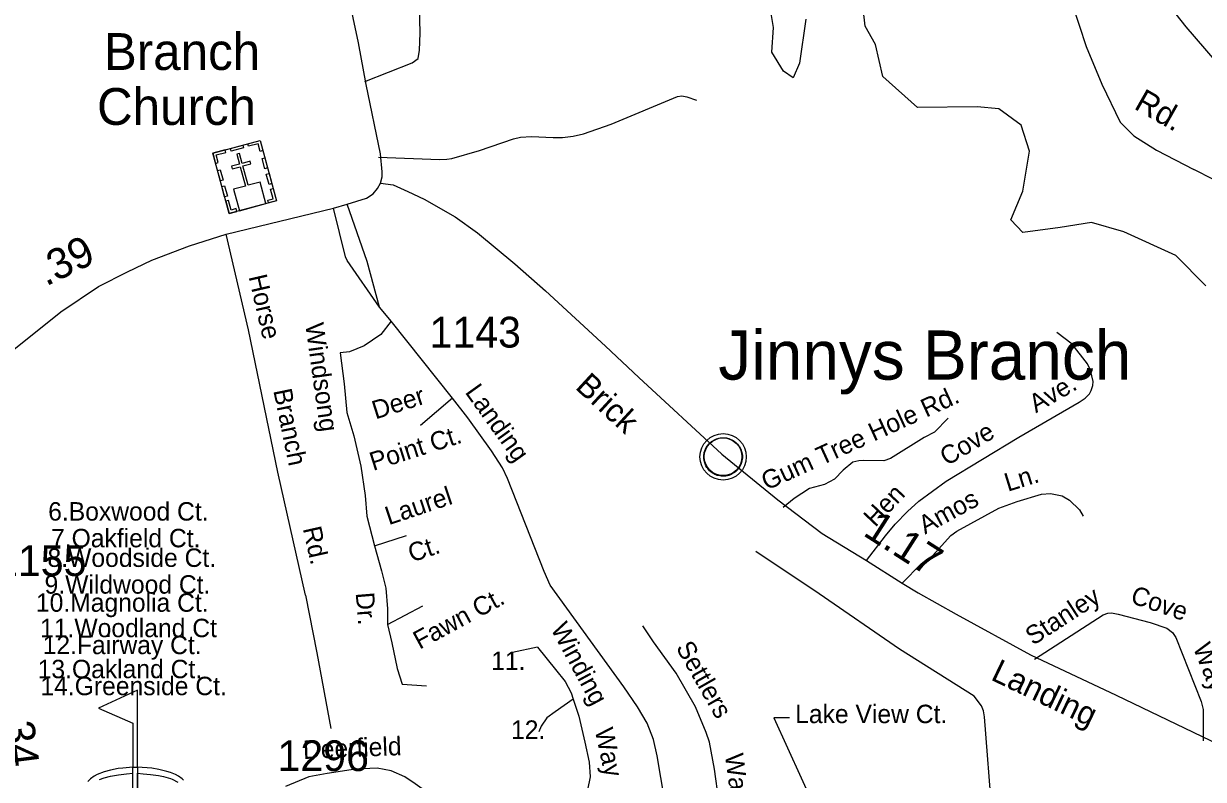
# Model space of a CAD drawing. Extents: x 2104537 to 2336408, y 34176 to 229611.
# Drawn here: x 2178229 to 2183028, y 59376 to 62451 of the extents above; entities that cross this region are included whole.
import ezdxf

# ---------------------------------------------------------------- set-up
doc = ezdxf.new("R2010")
doc.units = 0
for name, color, linetype in [('Exist Civil Demographics Community CELL', 7, 'Continuous'), ('Exist Civil Demographics Community Label', 7, 'Continuous'), ('Exist Cultural Church with Cemetary CELL', 7, 'Continuous'), ('Exist Cultural Church with Cemetery Label', 7, 'Continuous'), ('Exist Cultural Recreational Golf Course CELL', 7, 'Continuous'), ('Exist Hydrographic Creek Single Shore', 7, 'Continuous'), ('Exist Road Non-System Type 51', 7, 'Continuous'), ('Exist Road Non-System Type 51 Label', 7, 'Continuous'), ('Exist Road Primary NC Attributed', 7, 'Continuous'), ('Exist Road Primary NC Mileage Hundredths English Label', 7, 'Continuous'), ('Exist Road Secondary Mileage Hundredths English Label', 7, 'Continuous'), ('Exist Road Secondary Type 51 Attributed', 7, 'Continuous'), ('Exist Road Secondary Type 51 Label', 7, 'Continuous'), ('Exist Road Secondary Type 51 Number Label', 7, 'Continuous')]:
    doc.layers.add(name, color=color, linetype=linetype)

msp = doc.modelspace()

# ---------------------------------------------------------------- linework, layer by layer
at = {"layer": 'Exist Civil Demographics Community CELL'}
msp.add_lwpolyline([(2180997.1, 60700.7), (2180998.1, 60706.3), (2180999.9, 60712.8), (2181002.8, 60720), (2181005.7, 60725.8), (2181009.1, 60731.5), (2181012.8, 60736.6), (2181016.8, 60741), (2181021.4, 60745.6), (2181026.9, 60750.2), (2181032.3, 60753.8), (2181037.2, 60756.7), (2181042.3, 60759.2), (2181047.7, 60761.5), (2181053.4, 60763.3), (2181057.7, 60764.4), (2181062.5, 60765.2), (2181066.7, 60765.9), (2181073, 60766.2), (2181077.5, 60766), (2181083.1, 60765.8), (2181088, 60765.1), (2181092.9, 60764.1), (2181097.9, 60762.7), (2181103.1, 60760.7), (2181109.8, 60757.8), (2181116, 60754.3), (2181121.1, 60750.8), (2181126.3, 60746.7), (2181129.6, 60743.6), (2181133.7, 60739.2), (2181137.6, 60734.5), (2181140.6, 60729.9), (2181143.8, 60724.9), (2181146.2, 60719.8), (2181148.3, 60714.8), (2181149.8, 60709.7), (2181151.1, 60705.2), (2181152.2, 60699.1), (2181152.8, 60694.4), (2181153.1, 60688.4), (2181152.9, 60682.6), (2181152.3, 60676.9), (2181151.4, 60671.4), (2181149.7, 60665.3), (2181147.9, 60659.4), (2181145.6, 60654.4), (2181142.4, 60648.4), (2181139.1, 60643.1), (2181135.7, 60638.4), (2181131.4, 60633.6), (2181126.2, 60628.7), (2181121.1, 60624.5), (2181116.1, 60621.1), (2181111.8, 60618.6), (2181105, 60615.4), (2181097.8, 60612.6), (2181091.9, 60611.2), (2181085.3, 60609.9), (2181080.9, 60609.4), (2181076.4, 60609.1), (2181070.8, 60609.1), (2181066.5, 60609.6), (2181060.9, 60610.3), (2181055, 60611.6), (2181050.4, 60612.9), (2181045.2, 60614.8), (2181040.6, 60616.8), (2181036.7, 60619), (2181029.9, 60623.1), (2181024.3, 60627.4), (2181019.4, 60631.8), (2181014.9, 60636.7), (2181011.8, 60640.7), (2181008.8, 60644.8), (2181004.7, 60651.9), (2181003, 60655.5), (2181001.2, 60659.5), (2180998.7, 60667.7), (2180997.1, 60674.7), (2180996.4, 60679.9), (2180996.1, 60686.2), (2180996, 60690.9), (2180996.6, 60697.4)], close=True, dxfattribs=at)
for centre, radius in [((2181074.7, 60688.2), 94.3), ((2181074.5, 60688.5), 76.7)]:
    msp.add_circle(centre, radius, dxfattribs=at)
at = {"layer": 'Exist Cultural Church with Cemetary CELL'}
for points in [[(2178999.2, 61924.3), (2179191.4, 61976), (2179257.6, 61730.2), (2179065.4, 61678.4)], [(2179070.7, 61943.5), (2179120.7, 61957), (2179123.7, 61946), (2179073.6, 61932.5)], [(2179202.7, 61934.2), (2179191.8, 61931.2), (2179183.4, 61962.3), (2179144.3, 61951.8), (2179141.4, 61962.5), (2179191.5, 61976)], [(2179010.4, 61882.5), (2179021.4, 61885.4), (2179013, 61916.5), (2179052.2, 61927), (2179049.3, 61937.8), (2178999.2, 61924.3)], [(2179107, 61689.6), (2179215.2, 61718.8), (2179191.7, 61806.2), (2179142.7, 61793.1), (2179121.5, 61871.7), (2179153.4, 61880.3), (2179150.5, 61890.9), (2179118.6, 61882.4), (2179107.7, 61923.2), (2179096.5, 61920.1), (2179107.4, 61879.3), (2179075.5, 61870.7), (2179078.3, 61860.1), (2179110.3, 61868.7), (2179131.5, 61790.1), (2179083.4, 61777.1)], [(2179210.7, 61860.6), (2179199.5, 61902.5), (2179210.5, 61905.4), (2179221.7, 61863.6)], [(2179029.7, 61810.8), (2179018.4, 61852.7), (2179029.4, 61855.6), (2179040.7, 61813.8)], [(2179227.8, 61797), (2179216.6, 61838.8), (2179227.6, 61841.8), (2179238.8, 61799.9)], [(2179047.1, 61745.9), (2179035.9, 61787.8), (2179046.9, 61790.7), (2179058.1, 61748.9)], [(2179225.6, 61721.5), (2179222.6, 61732.6), (2179243.9, 61738.4), (2179233.4, 61777.4), (2179244.1, 61780.3), (2179257.6, 61730.2)], [(2179097.3, 61687), (2179094.3, 61698.1), (2179073.1, 61692.4), (2179062.5, 61731.4), (2179051.8, 61728.5), (2179065.3, 61678.4)]]:
    msp.add_lwpolyline(points, close=True, dxfattribs=at)
at = {"layer": 'Exist Cultural Recreational Golf Course CELL'}
for points in [[(2178879.9, 59371.9), (2178873.7, 59378.6), (2178858.9, 59388.4), (2178847.2, 59395.2), (2178826.4, 59403.7), (2178812.1, 59407.7), (2178779.1, 59416.4), (2178751.5, 59421.5), (2178692, 59425.4), (2178692, 59739.3), (2178533.5, 59665.9), (2178673.6, 59604.3), (2178673.6, 59425.4), (2178692, 59425.4), (2178692, 59400.4), (2178692, 59325.4), (2178692, 59400.4), (2178715.6, 59398.8), (2178746.1, 59395.5), (2178777.7, 59391.5), (2178798.8, 59387.2), (2178826.7, 59378.9), (2178833.6, 59376.8), (2178856.3, 59365)], [(2178673.6, 59325.4), (2178673.6, 59400.4), (2178673.6, 59425.4), (2178633.1, 59421.7), (2178613.6, 59420), (2178582.8, 59412.7), (2178557.3, 59406.4), (2178529, 59395.4), (2178516.6, 59388.3), (2178500.8, 59378.5), (2178490.6, 59367.5)], [(2178537.6, 59375.3), (2178556.7, 59381.8), (2178582.9, 59388.8), (2178615.7, 59394.8), (2178647.8, 59398.8), (2178673.6, 59400.4), (2178673.6, 59425.4), (2178692, 59425.4), (2178692, 59325.4)]]:
    msp.add_lwpolyline(points, dxfattribs=at)
at = {"layer": 'Exist Hydrographic Creek Single Shore'}
for points in [[(2181411.3, 62469.1), (2181385.5, 62289.5), (2181359.6, 62230.1), (2181320, 62257.5), (2181272.8, 62335.2), (2181278.9, 62435.6), (2181263.7, 62533.1)], [(2183037.6, 61384.6), (2182916.3, 61506.9), (2182704.8, 61604.3), (2182572.4, 61642.4), (2182446.1, 61621.1), (2182293.9, 61601.3), (2182245.2, 61653), (2182293.9, 61768.8), (2182321.3, 61931.7), (2182286.3, 62038.3), (2182196.5, 62103.7), (2182108.3, 62112.9), (2181864.8, 62109.8), (2181724.8, 62236.2), (2181694.4, 62365.6), (2181651.7, 62440.2), (2181638.1, 62574.2)]]:
    msp.add_lwpolyline(points, dxfattribs=at)
at = {"layer": 'Exist Road Non-System Type 51'}
for points in [[(2182747.7, 63064.6), (2182785.4, 62903.4), (2182829.6, 62736.4), (2182834.5, 62687.3), (2182857.5, 62627.4), (2182887, 62544.8), (2182916.5, 62489.8), (2182956.1, 62438), (2183074.5, 62301.5), (2183116.7, 62245.6), (2183140.4, 62202.9), (2183156.1, 62162.7), (2183163.9, 62121.4), (2183159.5, 62051.6), (2183146.7, 61907.2), (2183143.3, 61791.3)], [(2179616.7, 62215.3), (2179810.1, 62291), (2179833.7, 62309.2), (2179839.3, 62343.3), (2179843, 62412.7), (2179839.8, 62521.4), (2179841, 62551.9), (2179849.2, 62601.6), (2179842.3, 62701.5), (2179821.6, 62803.6), (2179823.3, 62823.2), (2179860.7, 62907.8), (2179933.3, 63046.5)], [(2179673.4, 61907.8), (2179921.3, 61898.4), (2179950.2, 61898.8), (2179971.6, 61902.4), (2180083.1, 61935), (2180221.5, 61981.9), (2180250.8, 61988.9), (2180294.8, 61991.3), (2180382.7, 61987), (2180420.7, 61988.2), (2180464.8, 61992.6), (2180506.7, 62002.9), (2180619.3, 62042.4), (2180889.5, 62154), (2180907.3, 62156.6), (2180927.5, 62152.6), (2180965.7, 62139.1)], [(2183143.3, 61791.3), (2183100.7, 61803.6), (2183068.8, 61817.4), (2182989.2, 61858)], [(2179676.8, 61297.8), (2179627.2, 61483.5), (2179545.1, 61716.7)], [(2179676.8, 61297.8), (2179545.2, 61486.7), (2179539, 61502.6), (2179489.3, 61700.4)], [(2179375.3, 60124.8), (2179262.9, 60626), (2179143.5, 61205.1), (2179053.9, 61594.6)], [(2179724.8, 61240.4), (2179719.4, 61247.1), (2179676.8, 61297.8)], [(2179724.8, 61240.4), (2179681.8, 61185.9), (2179614.9, 61140.1), (2179555.1, 61115.5), (2179516.3, 61112), (2179533.9, 60985.2), (2179544.5, 60868.9), (2179572.7, 60773.8), (2179600.8, 60650.6), (2179618.4, 60530.8), (2179625.5, 60446.3), (2179657.2, 60326.5), (2179685.3, 60224.4), (2179702.9, 60153.9), (2179710, 60069.4), (2179710, 60006), (2179727.6, 59932), (2179748.7, 59826.4), (2179769.8, 59763), (2179868.4, 59755.9)], [(2179973.7, 60926.3), (2179724.8, 61240.4)], [(2181658.3, 60266.8), (2181735.3, 60367.3), (2181774.9, 60413.8), (2181824.5, 60466.3), (2181870.3, 60508.4), (2181981.4, 60589.6), (2182277.9, 60768.3), (2182522.7, 60910.2), (2182546.7, 60926.5), (2182564.4, 60944.9), (2182572.2, 60958.8), (2182578.5, 60978.1), (2182579.8, 60994.8), (2182569.5, 61040.9), (2182557.2, 61066.7), (2182493.8, 61147), (2182432.1, 61193.5)], [(2179973.7, 60926.3), (2179843.5, 60815.7)], [(2180877.5, 58977.6), (2180878.8, 59047.5), (2180806.6, 59472.1), (2180791.1, 59537.4), (2180766.2, 59604.8), (2180726.5, 59671.5), (2180670.6, 59752), (2180371.8, 60166.6), (2180346.6, 60221.2), (2180197.1, 60600.1), (2180176.6, 60644.1), (2180133, 60712.5), (2180036.5, 60846.9), (2179973.7, 60926.3)], [(2181989.3, 60845.7), (2181933.8, 60789), (2181892, 60766.9), (2181754.8, 60681.6), (2181728.7, 60671.6), (2181644.1, 60673.5), (2181626.7, 60672.6), (2181601.6, 60666.2), (2181563, 60634.1), (2181527.2, 60597.4), (2181487.4, 60575.2), (2181425.4, 60559), (2181363.9, 60518.2), (2181318.6, 60482.3)], [(2181803.1, 60174.1), (2181880.4, 60252.6), (2181906.1, 60272.8), (2181926.3, 60284.9), (2182001.4, 60367.8), (2182025.1, 60386), (2182196.5, 60479.5), (2182270.2, 60506), (2182369.8, 60536.9), (2182406, 60539.1), (2182454, 60529.6), (2182483.9, 60512.3), (2182524.8, 60472.2), (2182538.7, 60446.3)], [(2179657.2, 60326.5), (2179786.6, 60368.3)], [(2182169.5, 59231), (2182138.1, 59630.9), (2182133.3, 59654.6), (2182124.9, 59674.7), (2182095.1, 59714.4), (2181791.4, 59905.9), (2181465.3, 60131), (2181207.8, 60303)], [(2179375.3, 60124.8), (2179422.5, 59890.2), (2179479.4, 59582.8)], [(2179710, 60006), (2179852.6, 60081.4)], [(2182341.8, 59864.5), (2182620.5, 60045.1), (2182639, 60051.7), (2182654.5, 60053.3), (2182682, 60048.5), (2182811.9, 60014.2), (2182879, 59991.3), (2182903, 59973.4), (2182915.4, 59953.5), (2183019.6, 59692.3), (2183027.5, 59659.6), (2183027, 59532.3)], [(2181099.1, 59021.6), (2181056.7, 59289.5), (2181039.8, 59417.1), (2181018.6, 59526.8), (2181006.3, 59567), (2180961.7, 59670.6), (2180883.3, 59808.3), (2180790.9, 59935.1), (2180748.6, 60000.8)], [(2180319, 59914.4), (2180218.6, 59892.5)], [(2180319, 59914.4), (2180392.9, 59822.8), (2180431.7, 59773.5), (2180456.3, 59727.7), (2180465.1, 59701.5)], [(2180465.1, 59701.5), (2180391.5, 59651.1), (2180357.4, 59626.1), (2180334.6, 59591.9), (2180325.5, 59569.1)], [(2180465.1, 59701.5), (2180488, 59632.6), (2180512.6, 59527), (2180530.2, 59445.9), (2180533.8, 59386.1), (2180523.2, 59333.2), (2180501.5, 59247.3)], [(2179903.6, 58878.9), (2179907.1, 58998.6), (2179903.6, 59097.2), (2179896.6, 59171.2), (2179882.5, 59241.7), (2179864.9, 59294.5), (2179850.8, 59336.8), (2179822.6, 59357.9), (2179780.4, 59386.1), (2179724, 59410.7), (2179667.7, 59421.3), (2179579.7, 59417.8), (2179463.5, 59400.2), (2179389.6, 59386.1), (2179294.5, 59347.3)]]:
    msp.add_lwpolyline(points, dxfattribs=at)
at = {"layer": 'Exist Road Non-System Type 51 Label'}
msp.add_lwpolyline([(2181345.2, 59626.7), (2181280.6, 59626.7), (2181447.4, 59260.4)], dxfattribs=at)
at = {"layer": 'Exist Road Primary NC Attributed'}
for points in [[(2179680.9, 61802), (2179688.3, 61827.6), (2179688.3, 61848.3), (2179681.4, 61921.6), (2179623.4, 62203.6), (2179591.6, 62372.3), (2179570.5, 62475.1), (2179505.4, 62800.1), (2179498.1, 62836.4), (2179488, 62876.3), (2179472.8, 62939.1), (2179456.2, 62984.7), (2179433.9, 63032), (2179396.2, 63118.3)], [(2177876.5, 60850.7), (2178175.8, 61114.2), (2178381.1, 61278), (2178534.4, 61381.7), (2178652.3, 61440.9), (2178750.3, 61488.6), (2178904, 61546.6), (2179053.9, 61594.6), (2179489.3, 61700.4), (2179545.1, 61716.7), (2179624.3, 61741.4), (2179650.9, 61758), (2179669.3, 61780.6), (2179680.9, 61802)]]:
    msp.add_lwpolyline(points, dxfattribs=at)
at = {"layer": 'Exist Road Secondary Type 51 Attributed'}
for points in [[(2182318.9, 64817.9), (2182331.9, 64284.9), (2182352.3, 63688.4), (2182364.6, 63424.2), (2182372.9, 63211), (2182387.2, 63064.6), (2182428.4, 62846.5), (2182451, 62713.8), (2182493.7, 62531.1), (2182551.2, 62358.2), (2182615.5, 62204.9), (2182689.1, 62049.7), (2182744.6, 61994.6), (2182836.9, 61936.7), (2182989.2, 61858)], [(2179680.9, 61802), (2179732.4, 61794.4), (2179792.5, 61767.4), (2179858.8, 61736.3), (2179984.7, 61664.3), (2180076, 61599.5), (2180227.8, 61474.2), (2180352.3, 61363.5), (2180596.3, 61138.7), (2180731.5, 61010.5), (2181069.4, 60699.4), (2181297.4, 60512.8), (2181478, 60376.9), (2181658.3, 60266.8), (2181803.1, 60174.1), (2181867.7, 60134.4), (2182022.9, 60048.3), (2182325.5, 59882.4), (2182673.8, 59718.5), (2183090.4, 59517.4)]]:
    msp.add_lwpolyline(points, dxfattribs=at)

# ---------------------------------------------------------------- texts
at = {"layer": 'Exist Civil Demographics Community Label'}
msp.add_text('Jinnys Branch', height=200, dxfattribs=at).set_placement((2181055.1, 61002.3))
at = {"layer": 'Exist Cultural Church with Cemetery Label'}
for s, p in [('Branch', (2178556, 62262.4)), ('Church', (2178528.1, 62038.8))]:
    msp.add_text(s, height=150, dxfattribs=at).set_placement(p)
at = {"layer": 'Exist Road Non-System Type 51 Label'}
for s, rotation, p in [('Horse', 282.9541, (2179144.1, 61421.6)), ('Windsong', 277.9033, (2179374.8, 61228.2)), ('Ave.', 30.098, (2182346.9, 60865.2)), ('Branch', 281.651, (2179244.7, 60957.9)), ('Deer', 17.6286, (2179660.7, 60840.1)), ('Landing', 305.674, (2180022.4, 60951)), ('Gum Tree Hole Rd.', 24.5875, (2181251.6, 60550.5)), ('Point Ct.', 17.6286, (2179651, 60630.7)), ('Cove', 31.0793, (2181985.2, 60649.3)), ('Ln.', 17.217, (2182232.6, 60545.8)), ('Laurel', 18.4516, (2179714.9, 60409.8)), ('Hen ', 46.6567, (2181693.2, 60398.9)), ('Amos', 28.6049, (2181895.9, 60371.6)), ('Rd.', 282.6385, (2179364.7, 60396.6)), ('Ct.', 18.4516, (2179808, 60258.1)), ('Dr.', 274.7616, (2179579.9, 60134.3)), ('Fawn Ct.', 28.4163, (2179840.1, 59902.9)), ('Stanley', 32.9467, (2182335.2, 59918.8)), ('Cove', 341.1303, (2182727.2, 60095.2)), ('Winding ', 298.2895, (2180371.5, 59989.2)), ('Settlers', 299.655, (2180880.8, 59912.1)), ('Way', 291.7518, (2182984.6, 59912.8)), ('Deerfield', 2.2915, (2179367, 59458.5)), ('Way', 282.2594, (2180552.2, 59576.6)), ('Way', 277.5414, (2181081.6, 59476.2))]:
    msp.add_text(s, height=75, rotation=rotation, dxfattribs=at).set_placement(p)
for s, p in [('6.Boxwood Ct.', (2178329.4, 60428.8)), ('7.Oakfield Ct.', (2178341, 60320.1)), ('8.Woodside Ct.', (2178326.7, 60240.3)), ('9.Wildwood Ct.', (2178314.7, 60131.5)), ('10.Magnolia Ct.', (2178279.5, 60057.8)), ('11.Woodland Ct', (2178296.5, 59954.4)), ('12.Fairway Ct.', (2178306.9, 59885.4)), ('11.', (2180131.1, 59820.8)), ('13.Oakland Ct.', (2178286.6, 59787.4)), ('14.Greenside Ct.', (2178297.8, 59718.4)), ('Lake View Ct.', (2181367.7, 59604.6)), ('12.', (2180211.8, 59540.7))]:
    msp.add_text(s, height=75, dxfattribs=at).set_placement(p)
at = {"layer": 'Exist Road Primary NC Mileage Hundredths English Label'}
msp.add_text('.39', height=125, rotation=25.9226, dxfattribs=at).set_placement((2178320.1, 61380.5))
at = {"layer": 'Exist Road Secondary Mileage Hundredths English Label'}
for s, rotation, p in [('1.17', 327.3877, (2181639.1, 60371.3)), ('.34', 277.3535, (2178140.6, 59652.6))]:
    msp.add_text(s, height=125, rotation=rotation, dxfattribs=at).set_placement(p)
at = {"layer": 'Exist Road Secondary Type 51 Label'}
for s, rotation, p in [('Rd.', 330.4315, (2182741.7, 62106.9)), ('Brick', 317.3412, (2180469, 60968.1)), ('Landing', 334.4437, (2182159.1, 59782.8))]:
    msp.add_text(s, height=95, rotation=rotation, dxfattribs=at).set_placement(p)
at = {"layer": 'Exist Road Secondary Type 51 Number Label'}
for s, p in [('1143', (2179880.4, 61133)), ('1155', (2178113.2, 60203.2)), ('1296', (2179262.2, 59409.6))]:
    msp.add_text(s, height=125, dxfattribs=at).set_placement(p)

doc.saveas('drawing.dxf')
